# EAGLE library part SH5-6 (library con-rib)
RIBBON CABLE CONNECTOR Flachstecker / Faston
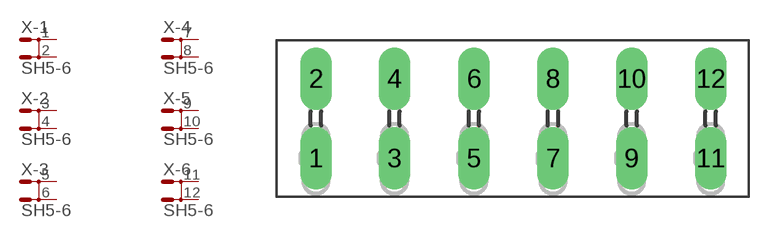
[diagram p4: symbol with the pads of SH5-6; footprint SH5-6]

Designator prefix X; gates -1=MD -2=MD -3=MD -4=MD -5=MD -6=MD

## SH5-6  [SH5-6]
1  -1:1  pas
2  -1:2  pas
3  -2:1  pas
4  -2:2  pas
5  -3:1  pas
6  -3:2  pas
7  -4:1  pas
8  -4:2  pas
9  -5:1  pas
10  -5:2  pas
11  -6:1  pas
12  -6:2  pas

## Footprint SH5-6 (pad centres in mm)
RIBBON CABLE CONNECTOR Flachstecker / Faston
drill 1.321 long: 1 -12.497,-2.515; 2 -12.497,2.515; 3 -7.518,-2.515; 4 -7.518,2.515; 5 -2.489,-2.515; 6 -2.489,2.515; 7 2.515,-2.515; 8 2.515,2.515; 9 7.493,-2.515; 10 7.493,2.515; 11 12.497,-2.515; 12 12.497,2.515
